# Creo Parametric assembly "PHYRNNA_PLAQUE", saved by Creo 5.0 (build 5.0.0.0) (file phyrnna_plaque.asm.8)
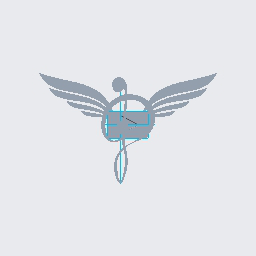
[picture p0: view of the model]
Units: Inch lbm Second (Pro/E Default); INCH, POUND, SECS

Created from: INLBS_ASM_DESIGN.ASM

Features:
  1. datum plane "ASM_RIGHT"
  2. datum plane "ASM_TOP"
  3. datum plane "ASM_FRONT"
  4. coordinate system
  5. component "PHYRNNA_TREBLE"
  6. component "PHYRNNA_PLAY_BUTTON"
  7. component "PHYRNNA_BACK_PIECE"
  8. component "PHYRNNA_WINGS_L"
  9. component "PHYRNNA_WINGS_R"
  10. datum plane "ADTM1"
  11. datum plane "ADTM2"
  12. sketch "Sketch 1"
  13. component "PHYRNNA_ACTUATOR_1"
  14. component "PHYRNNA_ACTUATOR_2"

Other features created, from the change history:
  component "PHYRNNA_TREBLE.PRT"
  component "PHYRNNA_BACK_PIECE.PRT"
  component "PHYRNNA_WINGS_L.PRT"
  component "PHYRNNA_ACTUATOR_1.PRT" (3 times)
